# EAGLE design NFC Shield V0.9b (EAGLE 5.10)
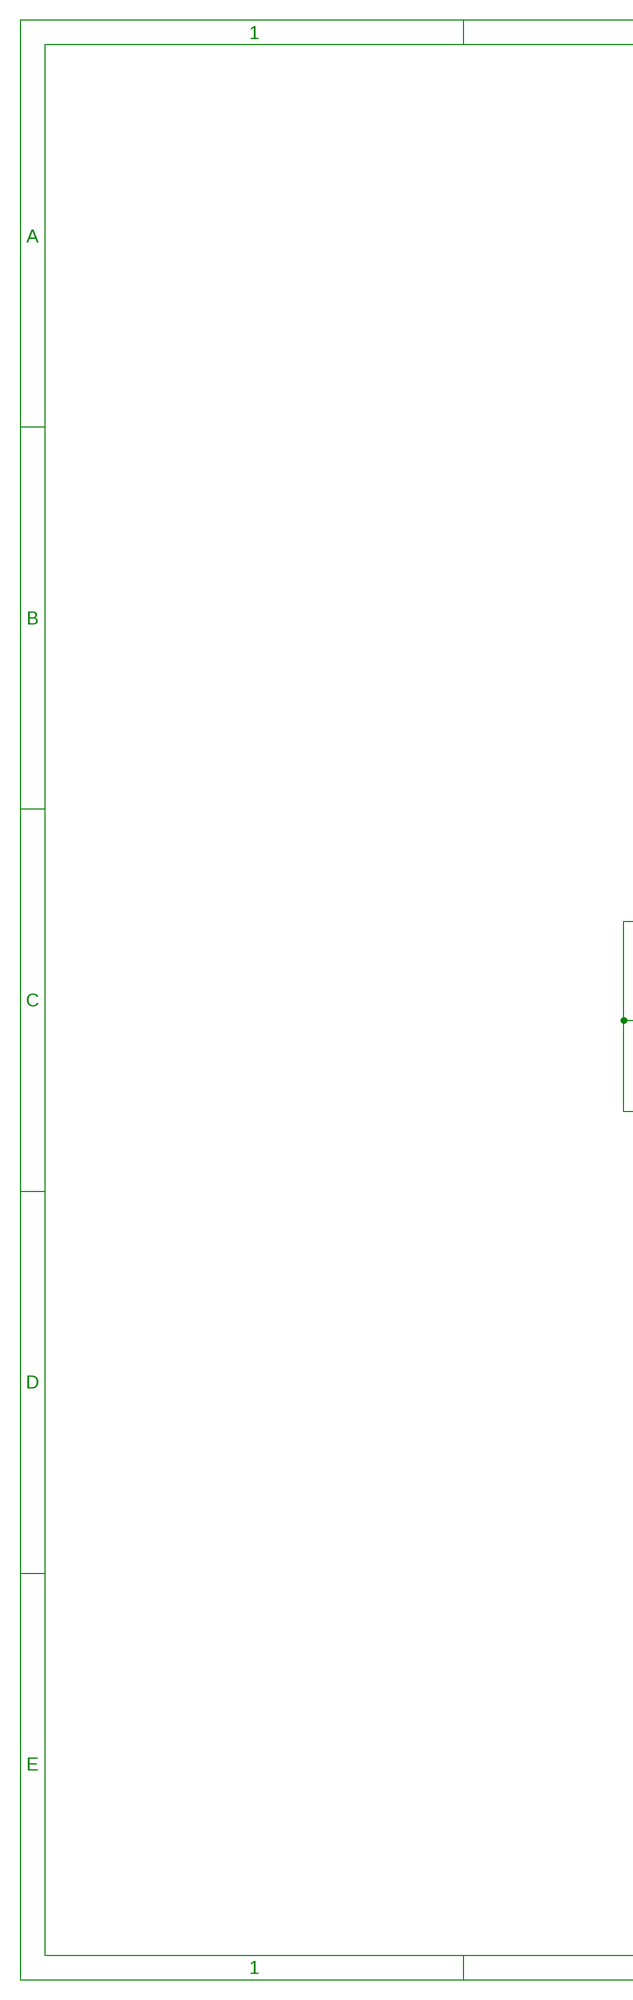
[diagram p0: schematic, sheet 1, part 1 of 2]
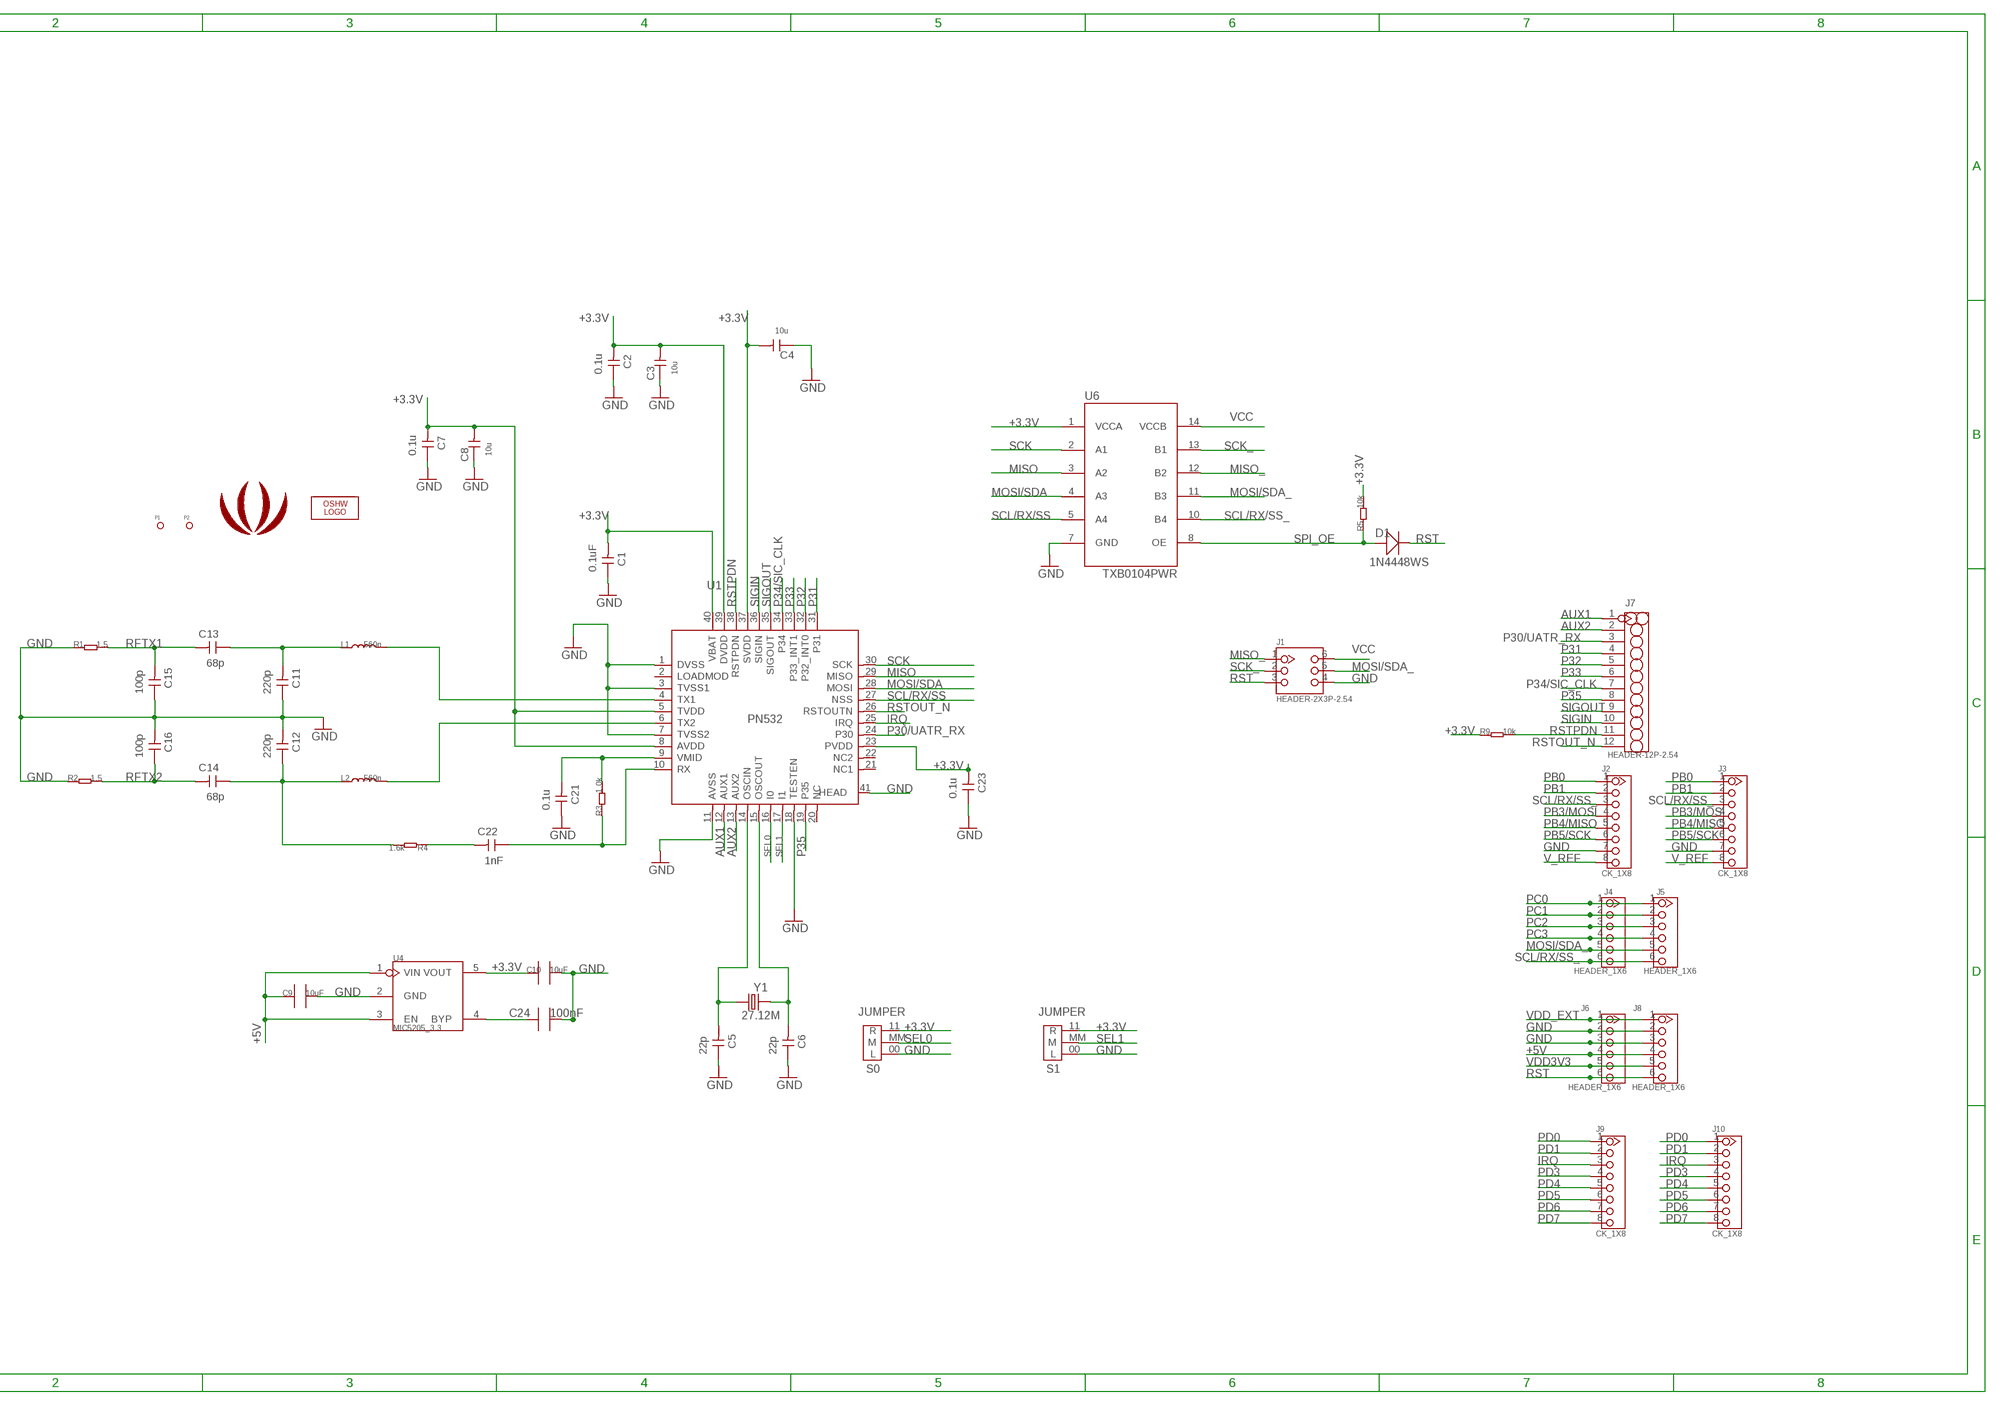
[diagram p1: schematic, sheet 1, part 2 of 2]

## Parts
C1  0.1uF  C-0603  [0603]
C2  0.1u  C-0603  [0603]
C3  10u  C-0805  [0805]
C4  10u  C-0805  [0805]
C5  22p  C-0603  [0603]
C6  22p  C-0603  [0603]
C7  0.1u  C-0603  [0603]
C8  10u  C-0805  [0805]
C9  10uF  C0805  [0805]
C10  10uF  C0805  [0805]
C11  220p  C-0603  [0603]
C12  220p  C-0603  [0603]
C13  68p  C-0603  [0603]
C14  68p  C-0603  [0603]
C15  100p  C-0603  [0603]
C16  100p  C-0603  [0603]
C21  0.1u  C-0603  [0603]
C22  1nF  C-0603  [0603]
C23  0.1u  C-0603  [0603]
C24  100nF  C0603  [0603]
D1  1N4448WS  D-0805  [D0805]
J1  HEADER-2X3P-2.54  [2X3P-2.54-LEADED]
J2  CK_1X8  CK_1X8DD  [CK_1X8]
J3  CK_1X8  CK_1X8DD  [CK_1X8]
J4  HEADER_1X6  [CK_1X6]
J5  HEADER_1X6  [CK_1X6]
J6  HEADER_1X6  [CK_1X6]
J7  HEADER-12P-2.54  [12P-2.54-DIP]
J8  HEADER_1X6  [CK_1X6]
J9  CK_1X8  CK_1X8DD  [CK_1X8]
J10  CK_1X8  CK_1X8DD  [CK_1X8]
L1  560n  L0805  [0805]
L2  560n  L0805  [0805]
LOGO1  LOGO-OSHW-FILLX0200-NT  [OSHW_FILLX200_NOTEXT]
P1  PAD-MARK  [ROUND-MARK-0.635]
P2  PAD-MARK  [ROUND-MARK-0.635]
R1  1.5  R-0603  [0603]
R2  1.5  R-0603  [0603]
R3  1.0k  R-0805  [0805]
R4  1.6k  R-0805  [0805]
R5  10k  R-0805  [0805]
R9  10k  R-0805  [0805]
S0  JUMPER  [JUMPER]
S1  JUMPER  [JUMPER]
U1  PN532  [HVQFN40]
U4  MIC5205_3.3  MIC5025_X.X  [SOT23-5]
U6  TXB0104PWR  [TSSOP14]
U$1  LOGO-SEEEDSTUDIO-SILK  [LOGO_SILK]
Y1  27.12M  CRYSTAL-HC49S  [HC49/S]

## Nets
+3.3V: C1.2 C2.2 C3.2 C4.2 C7.2 C8.2 C10.1 C23.2 R5.2 R9.1 S0.11(R) S1.11(R) U1.5(TVDD) U1.8(AVDD) U1.23(PVDD) U1.37(SVDD) U1.39(DVDD) U1.40(VBAT) U4.5(VOUT) U6.1(VCCA)
+5V: C9.1 J6.4 J8.4 U4.1(VIN) U4.3(EN)
AUX1: J7.1 U1.12(AUX1)
AUX2: J7.2 U1.13(AUX2)
GND: C1.1 C2.1 C3.1 C4.1 C5.1 C6.1 C7.1 C8.1 C9.2 C10.2 C11.1 C12.2 C15.1 C16.2 C21.1 C23.1 C24.2 J1.4 J2.7 J3.7 J6.2 J6.3 J8.2 J8.3 R1.1 R2.1 S0.00(L) S1.00(L) U1.1(DVSS) U1.3(TVSS1) U1.7(TVSS2) U1.11(AVSS) U1.18(TESTEN) U1.41(HEAD) U4.2(GND) U6.7(GND)
IRQ: J9.3 J10.3 U1.25(IRQ)
MISO: U1.29(MISO) U6.3(A2)
MISO_: J1.1 U6.12(B2)
MOSI/SDA: U1.28(MOSI) U6.4(A3)
MOSI/SDA_: J1.5 J4.5 J5.5 U6.11(B3)
N$1: C5.2 U1.14(OSCIN) Y1.1
N$2: C6.2 U1.15(OSCOUT) Y1.2
N$3: L2.2 U1.6(TX2)
N$4: L1.2 U1.4(TX1)
N$5: C11.2 C13.1 L1.1
N$6: C22.2 R4.1
N$7: C12.1 C14.1 L2.1 R4.2
N$9: C21.2 R3.2 U1.9(VMID)
N$11: C22.1 R3.1 U1.10(RX)
N$13: C24.1 U4.4(BYP)
P30/UATR_RX: J7.3 U1.24(P30)
P31: J7.4 U1.31
P32: J7.5 U1.32(P32_INT0)
P33: J7.6 U1.33(P33_INT1)
P34/SIC_CLK: J7.7 U1.34
P35: J7.8 U1.19(P35)
PB0: J2.1 J3.1
PB1: J2.2 J3.2
PB3/MOSI: J2.4 J3.4
PB4/MISO: J2.5 J3.5
PB5/SCK: J2.6 J3.6
PC0: J4.1 J5.1
PC1: J4.2 J5.2
PC2: J4.3 J5.3
PC3: J4.4 J5.4
PD0: J9.1 J10.1
PD1: J9.2 J10.2
PD3: J9.4 J10.4
PD4: J9.5 J10.5
PD5: J9.6 J10.6
PD6: J9.7 J10.7
PD7: J9.8 J10.8
RFTX1: C13.2 C15.2 R1.2
RFTX2: C14.2 C16.1 R2.2
RST: D1.- J1.3 J6.6 J8.6
RSTOUT_N: J7.12 U1.26(RSTOUTN)
RSTPDN: J7.11 R9.2 U1.38(RSTPDN)
SCK: U1.30(SCK) U6.2(A1)
SCK_: J1.2 U6.13(B1)
SCL/RX/SS: U1.27(NSS) U6.5(A4)
SCL/RX/SS_: J2.3 J3.3 J4.6 J5.6 U6.10(B4)
SEL0: S0.MM(M) U1.16(I0)
SEL1: S1.MM(M) U1.17(I1)
SIGIN: J7.10 U1.36(SIGIN)
SIGOUT: J7.9 U1.35(SIGOUT)
SPI_OE: D1.+ R5.1 U6.8(OE)
V_REF: J2.8 J3.8
VCC: J1.6 U6.14(VCCB)
VDD3V3: J6.5 J8.5
VDD_EXT: J6.1 J8.1
Unconnected: U1.2(LOADMOD) U1.20(NC) U1.21(NC1) U1.22(NC2)

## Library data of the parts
C1 C2 C5-C7 C11-C16 C21-C23 = Discrete:C*: Ceramic Capacitors
C3 C4 C8 = Discreter:C*: Ceramic Capacitors
C9 C10 = CPT_SMD:C0805
C24 = CPT_SMD:C0603; C0603: 100N
D1 = Discreter:D*
J1 = Connector:HEADER-2X3P
J2 J3 J9 J10 = CONNECTER:CK_1X8
J4-J6 J8 = CONNECTER:HEADER_1X6
J7 = Connector:HEADER-12P
L1 L2 = Discrete:L*
LOGO1 = Logo:LOGO-OSHW-FILL
P1 P2 = Discreter:PAD-MARK
R1-R5 R9 = Discrete:R*
S0 S1 = CPT_SMD:JUMPER
U1 = IC:PN532
U4 = ICs_v54:MIC5025_X.X
U6 = bibaja:TXB0104: 4-bit Bidirectional Voltage-Level Translator
U$1 = Logo:LOGO-SEEEDSTUDIO
Y1 = Discreter:CRYSTAL*: CRYSTAL

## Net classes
0 default: width 0.152 mm, drill 0.305 mm, clearance 0.152 mm
3 usbvcc: width 0.203 mm, drill 0.305 mm, clearance 0.203 mm

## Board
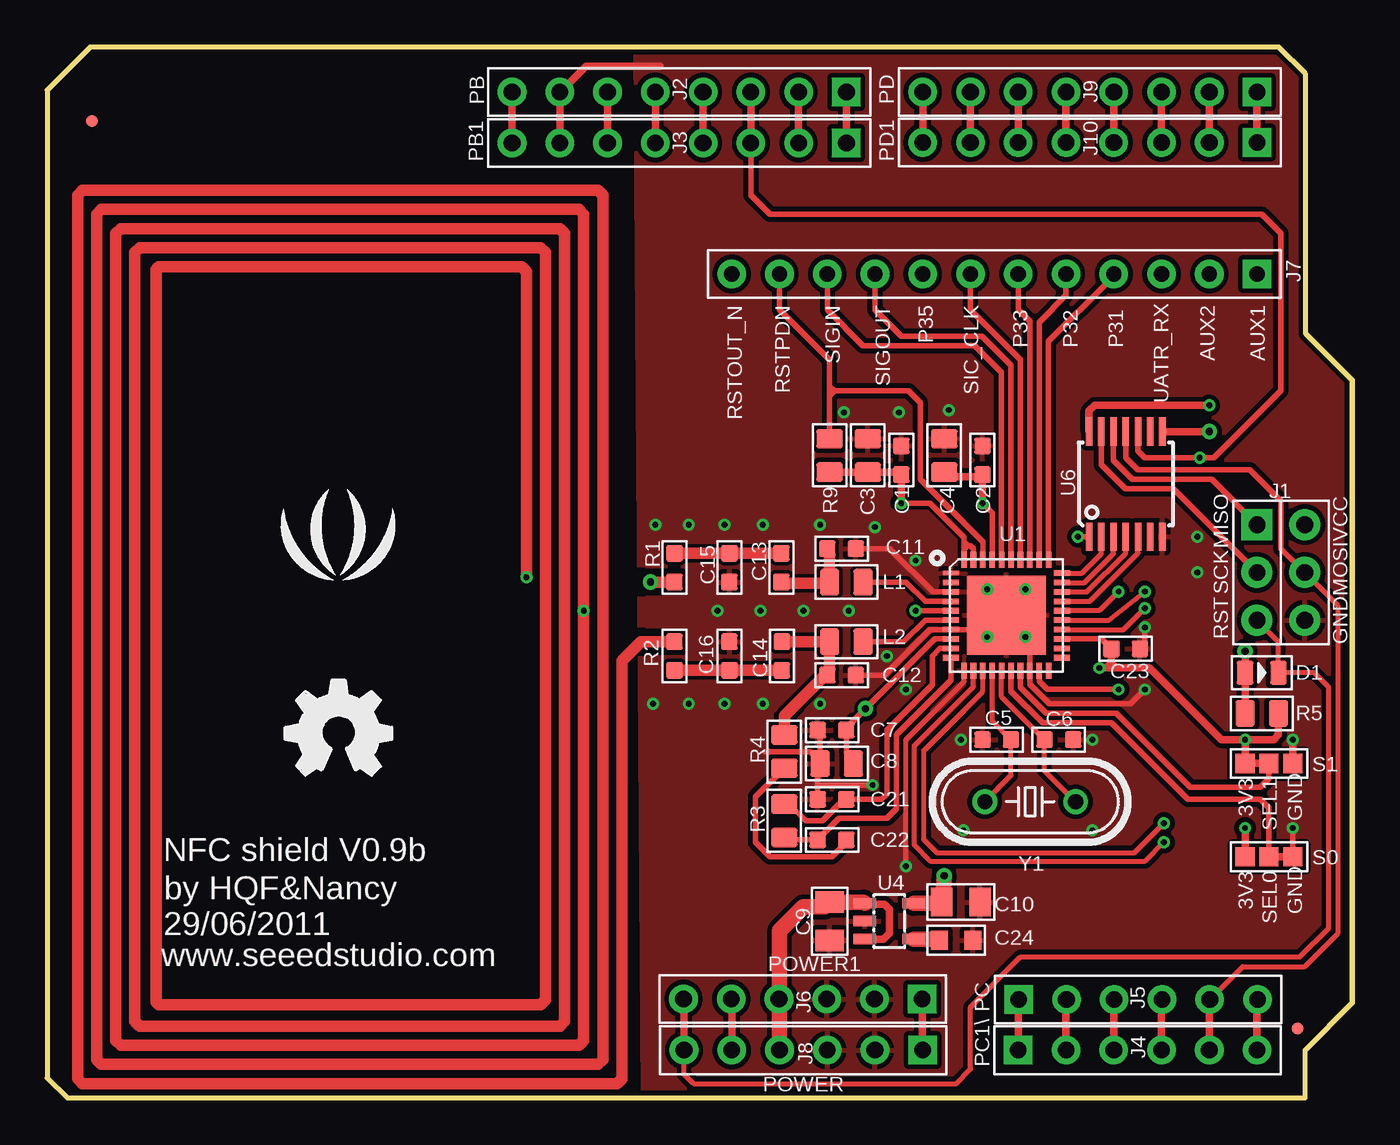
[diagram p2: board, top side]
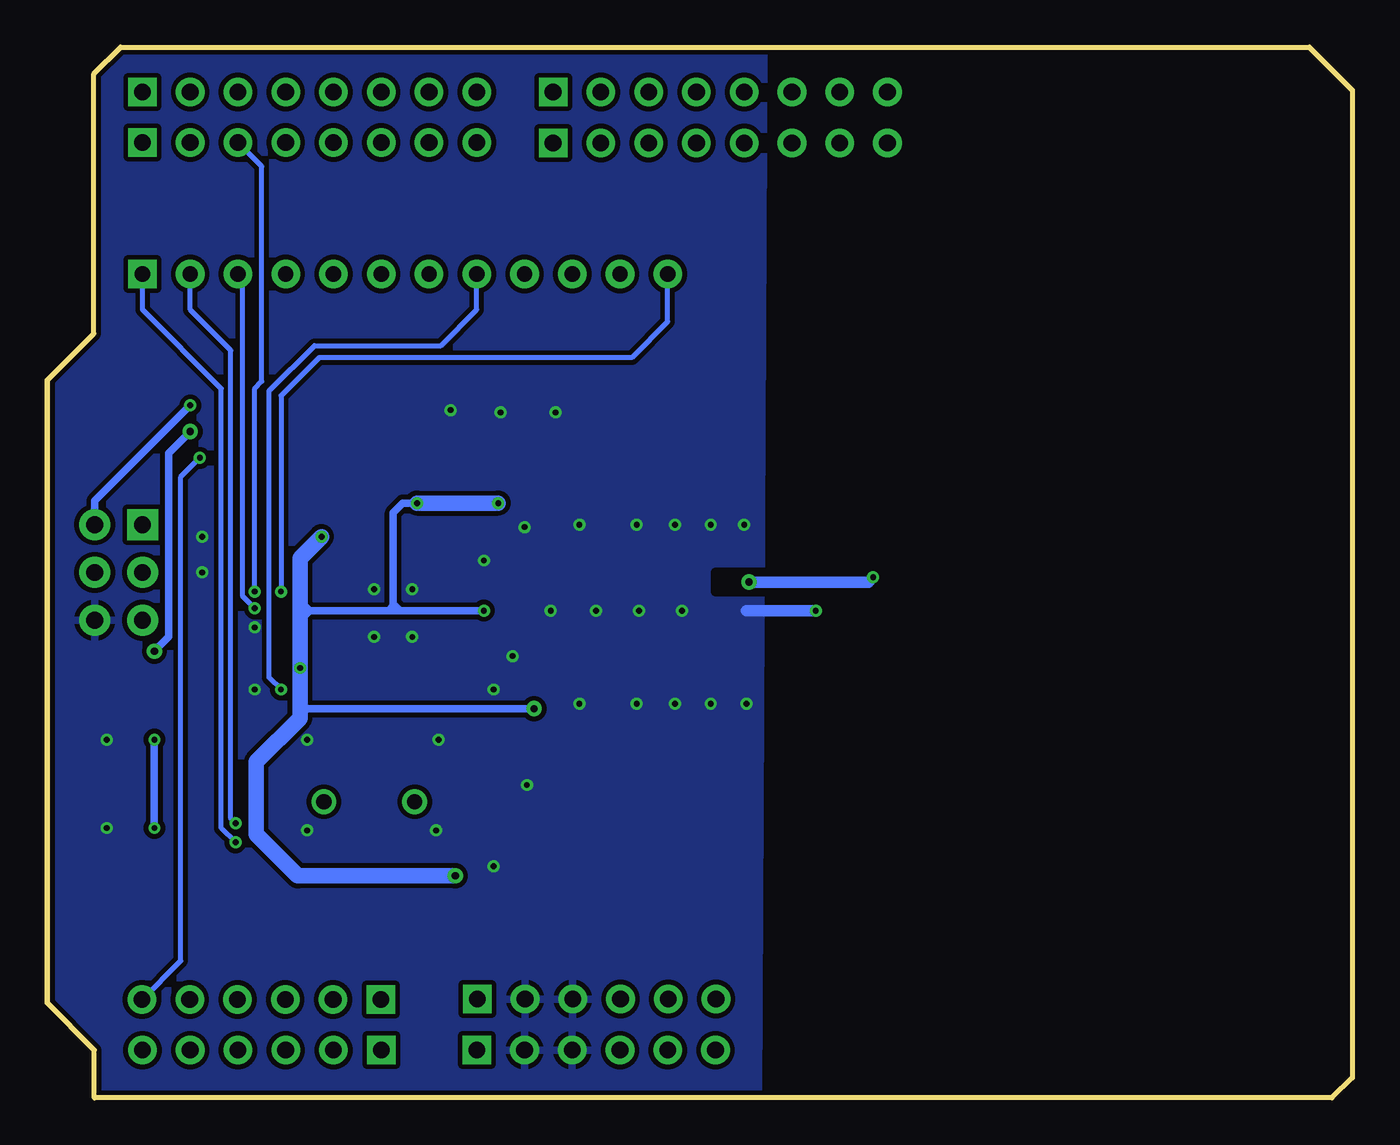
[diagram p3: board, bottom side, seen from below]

Size 69.44 x 55.88 mm. Coordinates in mm from the lower left corner, seen from the top.
Outline: 1.09,0 66.93,0 66.93,2.54 69.44,5.05 69.44,38.15 66.95,40.64 66.95,54.46 65.53,55.88 2.29,55.88 0,53.59 0,1.07 1.09,0
Copper layers (1*16): Top 0.035mm / dielectric 1.5mm / Bottom 0.035mm
Design rules "SeeedStudio_rule_no_angle_090911": minimum track width 6mil, minimum drill 12mil, track to track 6mil, track to pad 6mil, pad to pad 6mil, via to via 6mil, smd to smd 0mil, copper to edge 10mil, drill to drill 10mil, minimum pad ring 10mil, minimum via ring 6mil, stop-mask expansion 2mil, vias tented up to drill 100mil, thermal gap 10mil
tRestrict: area 31.6,26.9 to 33.9,27.9; area 31.6,23.7 to 33.9,24.8; area 63,17.1 to 66.9,18.4; area 63,12.1 to 67,13.5
bRestrict: area 31.6,26.9 to 33.9,27.9

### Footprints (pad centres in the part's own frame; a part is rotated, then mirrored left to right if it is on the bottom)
0603 = smd 0.889 x 0.889: 1 -0.762,0; 2 0.762,0
0805 = smd 1.016 x 1.397: 1 -0.889,0; 2 0.889,0
0805' = smd 1.143 x 1.524: 1 -1.016,0; 2 1.016,0
0603' = smd 0.889 x 1.016: 1 -0.889,0; 2 0.889,0
D0805 = smd 0.889 x 1.27: + -0.889,0; - 0.889,0
2X3P-2.54-LEADED = drill 0.889 pad 1.651 square: 1 -1.27,2.54 | drill 0.889 pad 1.651 round: 2 -1.27,0; 3 -1.27,-2.54; 4 1.27,-2.54; 5 1.27,0; 6 1.27,2.54
CK_1X8 = drill 0.889 pad 1.524 square: 1 0,8.89 | drill 0.889 pad 1.524 round: 2 0,6.35; 3 0,3.81; 4 0,1.27; 5 0,-1.27; 6 0,-3.81; 7 0,-6.35; 8 0,-8.89
CK_1X6 = drill 0.889 pad 1.524 square: 1 0,6.35 | drill 0.889 pad 1.524 round: 2 0,3.81; 3 0,1.27; 4 0,-1.27; 5 0,-3.81; 6 0,-6.35
12P-2.54-DIP = drill 0.813 pad 1.524 square: 1 0,13.97 | drill 0.813 pad 1.524 round: 2 0,11.43; 3 0,8.89; 4 0,6.35; 5 0,3.81; 6 0,1.27; 7 0,-1.27; 8 0,-3.81; 9 0,-6.35; 10 0,-8.89; 11 0,-11.43; 12 0,-13.97
ROUND-MARK-0.635 = smd 0.635 x 0.635: P$1 0,0
JUMPER = smd 1.016 x 1.016: 00 -1.27,0; 11 1.27,0; MM 0,0
HVQFN40 = smd 0.85 x 0.25: 1 -2.95,2.25 | smd 0.85 x 0.3: 2 -2.95,1.75; 3 -2.95,1.25; 4 -2.95,0.75; 5 -2.95,0.25; 6 -2.95,-0.25; 7 -2.95,-0.75; 8 -2.95,-1.25; 9 -2.95,-1.75; 10 -2.95,-2.25; 21 2.95,-2.25; 22 2.95,-1.75; 23 2.95,-1.25; 24 2.95,-0.75; 25 2.95,-0.25; 26 2.95,0.25; 27 2.95,0.75; 28 2.95,1.25; 29 2.95,1.75; 30 2.95,2.25 | smd 0.3 x 0.85: 11 -2.25,-2.95; 12 -1.75,-2.95; 13 -1.25,-2.95; 14 -0.75,-2.95; 15 -0.25,-2.95; 16 0.25,-2.95; 17 0.75,-2.95; 18 1.25,-2.95; 19 1.75,-2.95; 20 2.25,-2.95; 31 2.25,2.95; 32 1.75,2.95; 33 1.25,2.95; 34 0.75,2.95; 35 0.25,2.95; 36 -0.25,2.95; 37 -0.75,2.95; 38 -1.25,2.95; 39 -1.75,2.95; 40 -2.25,2.95 | smd 4.2 x 4.2: 41 0,0
SOT23-5 = smd 0.55 x 1.2: 1 -0.95,-1.3; 2 0,-1.3; 3 0.95,-1.3; 4 0.95,1.3; 5 -0.95,1.3
TSSOP14 = smd 0.35 x 1.5: 1 -1.95,-2.8; 2 -1.3,-2.8; 3 -0.65,-2.8; 4 0,-2.8; 5 0.65,-2.8; 6 1.3,-2.8; 7 1.95,-2.8; 8 1.95,2.8; 9 1.3,2.8; 10 0.65,2.8; 11 0,2.8; 12 -0.65,2.8; 13 -1.3,2.8; 14 -1.95,2.8
HC49/S = drill 0.813 round: 1 -2.413,0; 2 2.413,0

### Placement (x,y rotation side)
C1  45.44,33.91 270 top
C2  49.76,33.91 270 top
C3  43.66,34.16 270 top
C4  47.73,34.16 270 top
C5  50.52,19.05 0 top
C6  53.82,19.05 180 top
C7  41.76,19.56 0 top
C8  42.01,17.78 0 top
C9  10uF  [0805']  41.63,9.4 270 top
C10  10uF  [0805']  48.62,10.41 0 top
C11  42.27,29.21 180 top
C12  42.27,22.48 0 top
C13  39.07,28.19 90 top
C14  39.09,23.5 270 top
C15  36.3,28.19 90 top
C16  36.3,23.5 90 top
C21  41.76,15.88 0 top
C22  41.76,13.72 0 top
C23  57.38,23.88 180 top
C24  100nF  [0603']  48.36,8.38 0 top
D1  64.62,22.61 0 top
J1  65.63,27.94 0 top
J2  33.63,53.49 270 top
J3  33.63,50.77 270 top
J4  58.01,2.54 90 top
J5  58.04,5.23 90 top
J6  40.21,5.26 270 top
J7  50.39,43.82 270 top
J8  40.23,2.54 270 top
J9  55.47,53.49 270 top
J10  55.47,50.8 270 top
L1  42.52,27.43 0 top
L2  42.52,24.26 0 top
LOGO1  12.67,17.15 0 top
P1  2.39,51.94 0 top
P2  66.52,3.68 0 top
R1  33.38,28.19 90 top
R2  33.38,23.5 270 top
R3  39.22,14.73 90 top
R4  39.22,18.41 90 top
R5  64.62,20.45 0 top
R9  41.63,34.16 90 top
S0  65,12.83 180 top
S1  65,17.78 180 top
U1  51.03,25.65 0 top
U4  44.81,9.4 270 top
U6  57.38,32.64 0 top
U$1  15.47,29.21 0 top
Y1  52.3,15.75 0 top

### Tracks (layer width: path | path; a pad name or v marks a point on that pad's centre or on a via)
+3.3V  (via drill 0.3 pad 0.64, 0.38 pad 0.81)
  Top 0.305: U1.5 v46.21,25.9 v46.2,25.91 | U1.23 56.09,24.4 C23.2 56.62,23.62 | U1.8 47.24,24.4 v43.54,20.7 42.52,19.69 C7.2 42.52,18.41 42.9,18.03 C8.2 | U1.37 50.28,31.1 v49.76,31.62 | 49.76,33.02 C2.2 | 48.78,29.19 U1.40 | 48.78,29.19 48.96,29.36 | 48.96,29.36 49.12,29.36 49.28,29.21 U1.39 | 48.78,29.19 48.78,29.81 46.96,31.62 v45.44,31.62 | 48.96,29.36 48.96,29.38 48.87,29.46 | 48.23,33.02 47.98,33.02 C4.2 | U6.1 v54.84,29.85
  Top 0.406: C2.2 49.63,33.15 | R9.1 C3.2 45.31,33.27 C1.2 v45.44,31.62 | 48.23,33.02 49.76,33.02 v49.76,31.62 | 63.73,17.91 S1.11 v63.73,19.05 | v63.73,14.35 S0.11 | v63.73,19.05 65.25,19.05 65.51,19.3 R5.2 | v55.98,22.86 56.36,22.86 | 56.36,22.86 56.87,22.86 | 56.87,22.86 58.65,22.86 62.46,19.05 v63.73,19.05 | 56.62,23.11 C23.2 | 56.62,23.11 56.62,22.99 | 56.36,22.86 56.62,23.11 | 56.87,22.86 56.62,23.11
  Top 0.813: U4.5 47.66,10.35 C10.1 v47.73,11.81
  Bottom 0.406: 55.47,25.91 55.6,25.91 | 55.47,25.91 51.28,25.91 | 51.28,25.91 51.03,25.91 | 51.03,25.91 50.65,25.91 | 50.65,25.91 v46.2,25.91 | 55.47,25.91 55.85,26.29 | 55.98,20.32 55.6,20.7 | 55.6,20.7 v43.54,20.7 | 55.6,20.7 55.85,20.96 | v63.73,19.05 v63.73,14.35 | v49.76,31.62 50.52,31.62 51.03,31.12 51.03,26.29 | 51.03,25.91 51.03,26.16 | 51.03,26.16 51.03,26.29 | 51.28,25.91 51.03,26.16 | 51.03,26.29 50.65,25.91 | 55.98,25.4 55.47,25.91
  Bottom 0.813: v47.73,11.81 56.11,11.81 58.3,14.01 58.3,17.87 55.98,20.19 55.98,20.32 v55.98,22.86 55.98,25.4 55.98,28.7 v54.84,29.85 | v49.76,31.62 v45.44,31.62
+5V
  Top 0.406: U4.3 44.49,8.45 44.81,8.76 44.81,10.03 44.55,10.29 43.57,10.29 U4.1
  Top 0.813: J8.4 38.96,5.23 J6.4 38.96,5.28 38.96,8.89 40.23,10.16 41.38,10.16 C9.1 43.44,10.41 U4.1
AUX1  (via drill 0.3 pad 0.64)
  Top 0.254: U1.12 49.28,21.87 46.13,18.73 46.13,13.45 46.99,12.59 58.42,12.59 v59.41,13.59
  Bottom 0.254: v59.41,13.59 60.17,14.35 60.17,37.72 64.36,41.91 J7.1
AUX2  (via drill 0.3 pad 0.64)
  Top 0.254: U1.13 49.78,21.61 46.64,18.47 46.64,13.73 47.34,13.03 57.83,13.03 v59.41,14.61
  Bottom 0.254: v59.41,14.61 59.66,14.86 59.66,39.75 61.82,41.91 J7.2
GND  (via drill 0.3 pad 0.64, 0.38 pad 0.81)
  Top 0.203: R2.1 32.74,24.26
  Top 0.254: U1.11 48.78,22.13 45.69,19.05 v45.69,12.32
  Top 0.305: U1.3 47.11,26.9 44.81,29.21 C11.1 | 49.89,24.9 U1.7 46.98,24.9 44.55,22.48 C12.2 | 49.89,24.9 50.28,24.9 U1.41 52.28,24.4 52.28,24.11 | 49.5,24.38 49.5,24.52 49.89,24.9 | 58.14,24 C23.1 58.39,24.13 v58.39,25.02 | v58.39,21.72 57.63,20.96 53.31,20.96 52.28,21.99 U1.18 52.28,24.11 | 52.28,24.11 52.55,24.38 | C21.1 41,16.64 | 41,16.64 41,17.65 C8.1 41.12,17.91 | 41.12,17.91 41.12,19.43 C7.1 | 41,16.64 v43.92,16.64 | 41.12,17.91 40.61,18.41 38.2,18.41 | 65,12.83 65,12.8 | 66.27,12.8 S0.00 v66.27,14.35
  Top 0.406: J3.7 J2.7 27.3,53.49 28.68,54.86 32.61,54.86 | S1.00 v66.27,19.05 | 65,12.83 S0.00
  Top 0.61: R2.1 31.6,24.26 30.58,23.24 30.58,1.02 30.33,0.76 1.88,0.76 1.63,1.02 1.63,48.01 1.88,48.26 29.31,48.26 29.57,48.01 29.57,2.03 29.31,1.78 2.9,1.78 2.64,2.03 2.64,46.99 2.9,47.24 28.3,47.24 28.55,46.99 v28.55,25.91 28.55,3.05 28.3,2.79 3.91,2.79 3.66,3.05 3.66,45.97 3.91,46.23 27.28,46.23 27.53,45.97 27.53,4.06 27.28,3.81 4.93,3.81 4.67,4.06 4.67,44.96 4.93,45.21 26.26,45.21 26.52,44.96 26.52,5.21 26.26,4.95 5.94,4.95 5.82,5.08 5.82,44.07 5.94,44.2 25.25,44.2 25.5,43.94 v25.5,27.69 | v32.11,27.43 R1.1
  Bottom 0.61: v32.11,27.43 25.76,27.43 v25.5,27.69 | v28.55,25.91 32.23,25.91
  other vias: 48.62,19.05 55.6,19.05 48.74,14.22 55.6,14.22 45.69,21.72 42.65,25.91 32.23,20.96 44.04,30.35 46.2,28.57 42.39,36.45 45.31,36.45 47.98,36.58 44.68,23.5 50.01,27.05 52.04,27.05 50.01,24.51 52.04,24.51 34.14,20.96 36.04,20.96 38.07,20.96 41.12,20.96 40.23,25.91 37.95,25.91 35.66,25.91 32.36,30.48 34.14,30.48 36.04,30.48 38.07,30.48 41.12,30.48 61.19,29.85 61.19,27.94
  pour Bottom (isolate 0.254): 31.29,56.01 31.6,0 66.9,0 66.9,2.54 69.44,5.08 69.44,38.1 66.9,40.64 66.83,54.69 65.56,55.96
  pour Top (isolate 0.183): 31.98,31.24 48.87,31.24 49.12,30.99 49.12,20.57 32.23,20.57 31.98,20.83
  pour Top (isolate 0.254, rank 2): 31.34,56.01 65.61,55.96 66.88,54.69 66.9,40.64 69.44,38.1 69.44,5.08 66.9,2.54 66.9,0 31.72,0
IRQ  (via drill 0.3 pad 0.64)
  Top 0.254: U1.25 56.49,25.4 v58.39,26.92
  Top 0.406: J10.3 J9.3
  Bottom 0.254: v58.39,26.92 58.39,37.72 58.01,38.1 58.01,49.53 J10.3
MISO
  Top 0.254: U6.3 56.73,28.94 55.19,27.4 U1.29
MISO_
  Top 0.305: U6.12 56.73,33.9 57.73,32.89 61.95,32.89 J1.1
MOSI/SDA
  Top 0.254: U6.4 57.38,28.96 55.33,26.9 U1.28 54,26.92
MOSI/SDA_
  Top 0.254: 61.82,5.26 J5.5 63.6,6.98 66.9,6.98 68.68,8.76 68.68,26.16 J1.5
  Top 0.305: U6.11 57.38,34.04 58.01,33.4 63.98,33.4 65.63,31.75 65.63,29.21 J1.5
  Top 0.406: J4.5 61.82,5.21 J5.5
N$1
  Top 0.254: U1.14 50.28,20.05 C5.2 51.28,17.15 Y1.1
N$2
  Top 0.254: Y1.2 53.06,17.4 C6.2 52.04,20.07 50.78,21.33 U1.15
N$3
  Top 0.305: U1.6 46.71,25.4 45.57,24.26 L2.2
N$4
  Top 0.305: U1.4 46.72,26.4 45.69,27.43 L1.2
N$5
  Top 0.61: C11.2 41.63,29.08 L1.1 41.63,27.3 41.58,27.36 39.14,27.36 C13.1
N$6
  Top 0.305: C22.2 42.52,13.59 41.76,12.83 38.46,12.83 37.69,13.59 37.69,16 R4.1
N$7
  Top 0.61: C14.1 L2.1 41.63,22.61 C12.1 41.38,22.48 39.22,20.32 R4.2
N$9
  Top 0.305: U1.9 47.5,23.9 47.09,23.5 47.09,21.97 44.68,19.56 44.68,16.16 44.39,15.88 C21.2 42.39,15.88 41.25,14.73 40.36,14.73 39.47,15.62 R3.2
N$11
  Top 0.305: U1.10 48.08,22.2 45.19,19.3 45.19,15.37 44.68,14.86 42.14,14.86 C22.1 39.34,13.72 R3.1
N$13
  Top 0.813: U4.4 47.53,8.45 C24.1
P30/UATR_RX  (via drill 0.3 pad 0.64)
  Top 0.254: U1.24 57.26,24.9 v58.39,26.04
  Bottom 0.254: v58.39,26.04 59.03,26.67 59.03,43.56 J7.3
P31
  Top 0.305: U1.31 53.28,40.22 56.49,43.43 56.49,43.56 J7.4
P32
  Top 0.305: U1.32 52.78,41.25 54.2,42.67 J7.5
P33
  Top 0.305: U1.33 52.28,41.3 51.66,41.91 J7.6
P34/SIC_CLK
  Top 0.305: U1.34 51.78,39.26 49.12,41.91 J7.7
P35  (via drill 0.3 pad 0.64)
  Top 0.305: U1.19 52.78,22.15 53.21,21.72 v57,21.72
  Bottom 0.254: v57,21.72 57.63,22.35 57.63,37.59 55.22,40.01 48.49,40.01 46.58,41.91 J7.8
PB0
  Top 0.406: J3.1 J2.1
PB1
  Top 0.406: J3.2 J2.2
PB3/MOSI
  Top 0.406: J3.4 J2.4
PB4/MISO
  Top 0.406: J3.5 J2.5
PB5/SCK
  Top 0.406: J3.6 J2.6
PC0
  Top 0.406: J4.1 51.66,5.21 J5.1
PC1
  Top 0.406: J4.2 54.2,5.21 J5.2
PC2
  Top 0.406: J4.3 56.74,5.21 J5.3
PC3
  Top 0.406: J4.4 59.28,5.21 J5.4
PD0
  Top 0.406: J10.1 J9.1
PD1
  Top 0.406: J10.2 J9.2
PD3
  Top 0.406: J10.4 J9.4
PD4
  Top 0.406: J10.5 J9.5
PD5
  Top 0.406: J10.6 J9.6
PD6
  Top 0.406: J10.7 J9.7
PD7
  Top 0.406: J10.8 J9.8
RFTX1
  Top 0.61: R1.2 36.17,28.96 C15.2 C13.2
RFTX2
  Top 0.61: C14.2 C16.1 R2.2
RST
  Top 0.254: J8.6 33.88,1.27 34.39,0.76 48.36,0.76 49.12,1.52 49.12,4.83 51.79,7.49 66.65,7.49 68.17,9.02 68.17,21.84 67.41,22.61 D1.- 65.51,24.26 J1.3
  Top 0.406: J8.6 33.88,5.23 J6.6
RSTOUT_N  (via drill 0.3 pad 0.64)
  Top 0.254: U1.26 55.98,25.9 v57,26.92
  Bottom 0.254: v57,26.92 57,37.34 54.97,39.37 38.33,39.37 36.42,41.27 J7.12
RSTPDN
  Top 0.305: U1.38 49.78,29.57 46.46,32.89 46.46,36.96 45.82,37.59 41.88,37.59 | 41.63,37.34 R9.2 | 41.63,37.34 41.63,37.85 | 41.63,37.85 41.63,39.24 38.96,41.91 J7.11 | 41.88,37.59 41.63,37.34 | 41.88,37.59 41.63,37.85
SCK
  Top 0.254: U6.2 56.08,28.93 55.06,27.9 U1.30
SCK_
  Top 0.305: U6.13 56.08,33.68 57.37,32.38 59.92,32.38 J1.2
SCL/RX/SS
  Top 0.254: U6.5 58.03,28.97 55.46,26.4 U1.27
SCL/RX/SS_  (via drill 0.3 pad 0.64)
  Top 0.305: U6.10 58.01,35.42 58.01,34.42 58.39,34.04 v61.32,34.04 62.08,34.04 65.63,37.59 65.63,45.97 64.62,46.99 38.46,46.99 37.44,48.01 37.44,50.93
  Top 0.406: J4.6 64.36,5.21 J5.6 | J3.3 37.44,50.93 J2.3
  Bottom 0.254: v61.32,34.04 62.33,33.02 62.33,7.29 J5.6
SEL0
  Top 0.305: U1.16 51.28,21.63 52.97,19.94 56.62,19.94 60.68,15.88 64.54,15.88 65,15.42 S0.MM
SEL1
  Top 0.305: U1.17 51.78,21.83 53.16,20.45 56.87,20.45 60.81,16.51 64.54,16.51 65,16.97 S1.MM | 63.7,17.8 63.7,17.78
  Top 0.406: 63.7,17.8 65,17.8 S1.MM
SIGIN
  Top 0.305: U1.36 50.78,38.59 49.36,40.01 43.41,40.01 41.5,41.91 J7.10
SIGOUT
  Top 0.305: U1.35 51.28,38.95 49.72,40.51 45.44,40.51 44.04,41.91 J7.9
SPI_OE  (via drill 0.38 pad 0.81)
  Top 0.406: R5.1 D1.+ v63.73,23.75 | v61.82,35.43 59.33,35.43 U6.8
  Bottom 0.406: v63.73,23.75 62.97,24.51 62.97,34.29 v61.82,35.43
V_REF
  Top 0.406: J3.8 J2.8
VCC  (via drill 0.3 pad 0.64)
  Top 0.406: U6.14 55.43,36.53 55.73,36.83 v61.82,36.83
  Bottom 0.406: v61.82,36.83 66.9,31.75 J1.6
VDD3V3
  Top 0.406: J8.5 36.42,5.23 J6.5
VDD_EXT
  Top 0.406: J6.1 46.56,2.57 J8.1

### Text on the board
tPlace: PB | PD | PB1 | PD1 | RSTOUT_N | RSTPDN | SIGIN | SIGOUT | P35 | SIC_CLK | AUX2 | AUX1 | P33 | P32 | P31 | UATR_RX | MISO | VCC | SCK | MOSI | RST | GND | 3V3 | SEL1 | GND | NFC shield V0.9b | 3V3 | SEL0 | by HQF&Nancy | GND | 29/06/2011 | www.seeedstudio.com | POWER1 | PC | POWER | PC1\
